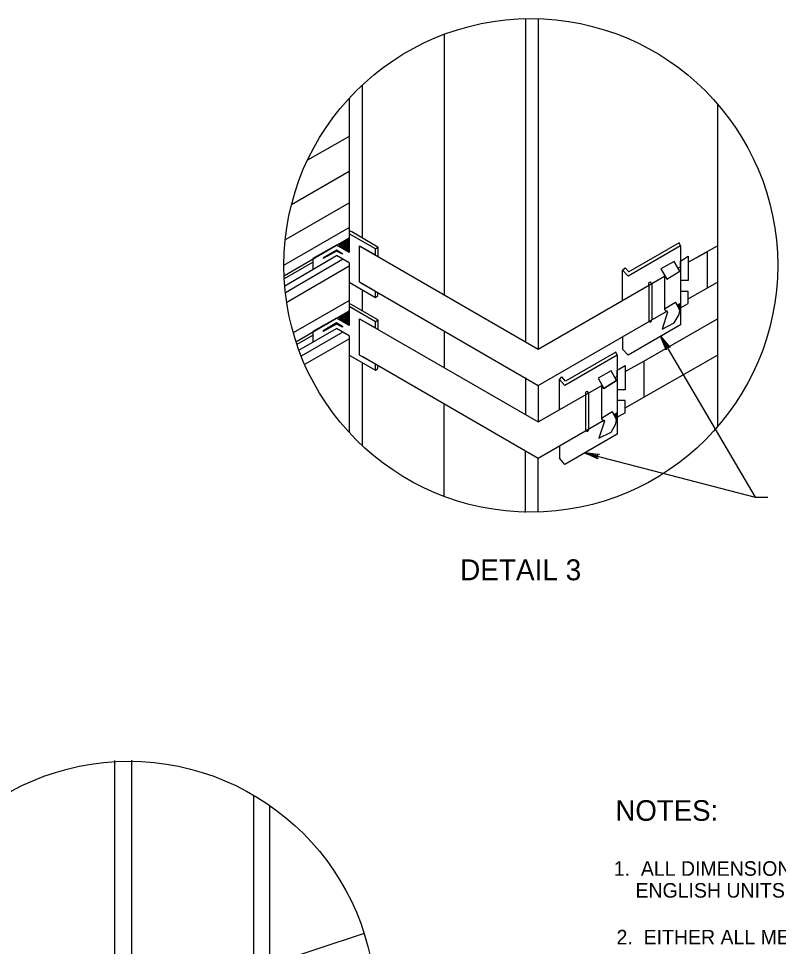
# Model space of a CAD drawing. Extents: x 650495 to 651400, y 297864 to 299646.
# Drawn here: x 650997.2 to 651153.6, y 298064.9 to 298255.9 of the extents above; entities that cross this region are included whole.
import ezdxf

# ---------------------------------------------------------------- set-up
doc = ezdxf.new("R2010")
doc.units = 0
doc.layers.add('2', color=7, linetype='Continuous')
doc.layers.add('3', color=7, linetype='Continuous')

# ---------------------------------------------------------------- blocks, each defined once
blk = doc.blocks.new('RARROW')
at = {"layer": '3'}
blk.add_lwpolyline([(-2.2695, 0.285), (-2.184875, 0.12075), (0, 0), (-2.2695, 0.285), (-2.38575, 0.384625), (0, 0), (-2.183125, -0.108), (-2.262875, -0.2705), (0, 0), (-2.38575, -0.379125), (-2.262875, -0.2705)], dxfattribs=at)

msp = doc.modelspace()

# ---------------------------------------------------------------- linework, layer by layer
at = {"layer": '2'}
for p, q in [((651101.56, 298255.88), (651101.56, 298189.5)), ((651104.19, 298255.88), (651104.19, 298187.88)), ((651084.81, 298252.63), (651084.81, 298199.13)), ((651067.94, 298242.25), (651067.94, 298210.75)), ((651065.31, 298239.5), (651065.31, 298207.75)), ((651141.06, 298238.38), (651141.06, 298171.88)), ((651065.31, 298231.63), (651056.69, 298226.75)), ((651053.44, 298217.63), (651065.31, 298224.5)), ((651052.31, 298210.5), (651065.31, 298218)), ((651051.81, 298205.13), (651065.31, 298212.88)), ((651051.94, 298203), (651065.31, 298210.75)), ((651063.31, 298208.88), (651065.31, 298210)), ((651065.31, 298207.75), (651062.69, 298209.25)), ((651071.19, 298208.88), (651071.19, 298207)), ((651133.44, 298209.13), (651122.69, 298202.88)), ((651133.19, 298209.75), (651122.81, 298203.75)), ((651133.44, 298209.13), (651133.19, 298209.75)), ((651133.44, 298209.13), (651133.44, 298192.88)), ((651141.06, 298209.13), (651141.06, 298201.63)), ((651052.06, 298200.88), (651062.69, 298207.13)), ((651052.19, 298199.5), (651063.94, 298206.38)), ((651057.81, 298206.5), (651057.81, 298204.25)), ((651059.94, 298206.63), (651059.94, 298206.5)), ((651065.31, 298205.63), (651062.69, 298207.13)), ((651063.94, 298207.5), (651063.94, 298207.38)), ((651135.06, 298205.75), (651138.94, 298207.88)), ((651138.94, 298207.88), (651138.94, 298200.38)), ((651051.94, 298202.38), (651057.81, 298205.75)), ((651052.44, 298197.5), (651065.31, 298205)), ((651065.31, 298205.63), (651065.31, 298192.75)), ((651121.56, 298204.13), (651122.06, 298204.63)), ((651122.81, 298203.75), (651122.06, 298204.63)), ((651121.56, 298197.88), (651121.56, 298204.13)), ((651122.69, 298202.88), (651121.56, 298204.13)), ((651130.19, 298202.88), (651130.19, 298196)), ((651126.94, 298201), (651126.94, 298193.5)), ((651127.56, 298201.38), (651127.56, 298193.88)), ((651128.06, 298201.63), (651128.06, 298201.63)), ((651067.94, 298200.13), (651067.94, 298195.75)), ((651053.81, 298191.25), (651065.31, 298197.88)), ((651130.19, 298196.13), (651132.44, 298197.5)), ((651054.31, 298189.38), (651065.31, 298195.75)), ((651063.31, 298193.88), (651065.31, 298195)), ((651065.31, 298192.75), (651062.69, 298194.25)), ((651071.19, 298193.88), (651071.19, 298192)), ((651133.44, 298192.88), (651122.69, 298186.63)), ((651141.06, 298194.13), (651141.06, 298186.63)), ((651054.94, 298187.63), (651062.69, 298192.13)), ((651055.44, 298186.5), (651063.94, 298191.38)), ((651057.81, 298191.5), (651057.81, 298189.25)), ((651059.94, 298191.63), (651059.94, 298191.5)), ((651065.31, 298190.63), (651062.69, 298192.13)), ((651063.94, 298192.5), (651063.94, 298192.38)), ((651084.81, 298191.63), (651084.81, 298184.13)), ((651054.56, 298188.88), (651057.81, 298190.75)), ((651056.19, 298184.75), (651065.31, 298190)), ((651065.31, 298190.63), (651065.31, 298170.75)), ((651121.56, 298190.38), (651121.56, 298187.88)), ((651129.38, 298190.52), (651148.81, 298157.38)), ((651120.19, 298187.25), (651109.81, 298181.25)), ((651120.44, 298186.63), (651120.19, 298187.25)), ((651122.69, 298186.63), (651121.56, 298187.88)), ((651067.94, 298185.13), (651067.94, 298168)), ((651120.44, 298186.63), (651109.69, 298180.38)), ((651120.44, 298186.63), (651120.44, 298170.38)), ((651122.06, 298183.25), (651125.94, 298185.38)), ((651125.94, 298185.38), (651125.94, 298177.88)), ((651128.06, 298186.63), (651128.06, 298186.63)), ((651101.56, 298182), (651101.56, 298174.5)), ((651108.56, 298181.63), (651109.06, 298182.13)), ((651109.69, 298180.38), (651108.56, 298181.63)), ((651108.56, 298175.38), (651108.56, 298181.63)), ((651109.81, 298181.25), (651109.06, 298182.13)), ((651104.19, 298180.38), (651104.19, 298172.88)), ((651117.19, 298180.38), (651117.19, 298173.5)), ((651113.94, 298178.5), (651113.94, 298171)), ((651114.56, 298178.88), (651114.56, 298171.38)), ((651084.81, 298157.5), (651084.81, 298176.63)), ((651117.19, 298173.63), (651119.44, 298175)), ((651120.44, 298170.38), (651109.69, 298164.13)), ((651101.56, 298154.25), (651101.56, 298167)), ((651108.56, 298167.88), (651108.56, 298165.38)), ((651113.69, 298166.5), (651148.81, 298157.38)), ((651104.19, 298154.38), (651104.19, 298165.38)), ((651109.69, 298164.13), (651108.56, 298165.38)), ((651148.81, 298157.38), (651151.44, 298157.38)), ((651148.81, 298157.38), (651151.44, 298157.38)), ((651017.06, 298034.38), (651017.06, 298103.13)), ((651020.56, 298034.38), (651020.56, 298103.25)), ((651045.69, 298023.13), (651045.69, 298096)), ((651048.94, 298024.88), (651048.94, 298093.88)), ((651048.94, 298061.13), (651068.44, 298067.63))]:
    msp.add_line(p, q, dxfattribs=at)
for points in [[(651070.69, 298208.5), (651071.19, 298208.88), (651065.81, 298212), (651065.31, 298212.25)], [(651065.19, 298210.38), (651063.19, 298209.25), (651065.06, 298208.13), (651065.06, 298210.25), (651063.56, 298209.25), (651064.81, 298208.38), (651064.94, 298209.88), (651063.94, 298209.25), (651064.69, 298208.63), (651064.69, 298209.5), (651064.31, 298209.25), (651064.56, 298209), (651064.56, 298209.25)], [(651067.44, 298201.63), (651067.44, 298209.13), (651070.69, 298207.25), (651070.69, 298208.5), (651065.31, 298211.63), (651065.31, 298207.75)], [(651065.31, 298207.75), (651062.69, 298209.25), (651057.81, 298206.5)], [(651063.94, 298207.5), (651062.69, 298208.25), (651059.94, 298206.63)], [(651067.44, 298209.13), (651104.19, 298187.88), (651130.19, 298202.88)], [(651135.06, 298205.75), (651141.06, 298209.13)], [(651063.94, 298207.38), (651062.69, 298208), (651059.94, 298206.5)], [(651133.44, 298204.75), (651133.44, 298206), (651135.06, 298207), (651135.06, 298202), (651133.44, 298202)], [(651065.31, 298205.63), (651065.31, 298204.13), (651065.31, 298201.63), (651070.69, 298198.5), (651070.69, 298199.75), (651067.44, 298201.63)], [(651132.94, 298204.5), (651133.44, 298204.75)], [(651067.94, 298201.38), (651104.19, 298180.38), (651130.81, 298195.75)], [(651135.06, 298198.25), (651141.06, 298201.63)], [(651070.69, 298198.5), (651071.19, 298198.88), (651071.19, 298199.5)], [(651133.44, 298196.38), (651134.56, 298197), (651135.06, 298197.25), (651135.06, 298199.75), (651133.44, 298199.75)], [(651070.69, 298193.5), (651071.19, 298193.88), (651065.81, 298197), (651065.31, 298197.25)], [(651067.44, 298186.63), (651067.44, 298194.13), (651070.69, 298192.25), (651070.69, 298193.5), (651065.31, 298196.63), (651065.31, 298192.75)], [(651130.19, 298196), (651130.44, 298195.75), (651130.69, 298195.75), (651130.81, 298195.5), (651129.69, 298192), (651132.19, 298193.25), (651133.19, 298195), (651133.31, 298195.88), (651132.44, 298197.5)], [(651132.44, 298197.5), (651133.31, 298195.88), (651133.44, 298197.25), (651132.81, 298196.88), (651133.19, 298196.25), (651133.19, 298197.13), (651132.94, 298196.88), (651133.19, 298196.5)], [(651132.81, 298196.88), (651133.44, 298197.25)], [(651065.19, 298195.38), (651063.19, 298194.25), (651065.06, 298193.13), (651065.06, 298195.25), (651063.56, 298194.25), (651064.81, 298193.38), (651064.94, 298194.88), (651063.94, 298194.25), (651064.69, 298193.63), (651064.69, 298194.5), (651064.31, 298194.25), (651064.56, 298194), (651064.56, 298194.25)], [(651130.81, 298195.5), (651129.69, 298192)], [(651065.31, 298192.75), (651062.69, 298194.25), (651057.81, 298191.5)], [(651063.94, 298192.5), (651062.69, 298193.25), (651059.94, 298191.63)], [(651063.94, 298192.38), (651062.69, 298193), (651059.94, 298191.5)], [(651067.44, 298194.13), (651104.19, 298172.88), (651117.31, 298180.38)], [(651125.94, 298185.38), (651141.06, 298194.13)], [(651065.31, 298190.63), (651065.31, 298189.13), (651065.31, 298186.63), (651070.69, 298183.5), (651070.69, 298184.75), (651067.44, 298186.63)], [(651067.94, 298186.38), (651104.19, 298165.38), (651117.69, 298173.25)], [(651122.06, 298175.75), (651141.06, 298186.63)], [(651070.69, 298183.5), (651071.19, 298183.88), (651071.19, 298184.5)], [(651120.44, 298182.25), (651120.44, 298183.5), (651122.06, 298184.5), (651122.06, 298179.5), (651120.44, 298179.5)], [(651119.94, 298182), (651120.31, 298181.38), (651117.69, 298179.75), (651117.19, 298180.38)], [(651119.94, 298182), (651120.44, 298182.25)], [(651120.44, 298173.88), (651121.56, 298174.5), (651122.06, 298174.75), (651122.06, 298177.25), (651120.44, 298177.25)], [(651117.19, 298173.5), (651117.44, 298173.25), (651117.69, 298173.25), (651117.81, 298173), (651116.69, 298169.5), (651119.19, 298170.75), (651120.19, 298172.5), (651120.31, 298173.38), (651119.44, 298175)], [(651119.44, 298175), (651120.31, 298173.38), (651120.44, 298174.75), (651119.81, 298174.38), (651120.19, 298173.75), (651120.19, 298174.63), (651119.94, 298174.38), (651120.19, 298174)], [(651119.81, 298174.38), (651120.44, 298174.75)], [(651117.81, 298173), (651116.69, 298169.5)]]:
    msp.add_lwpolyline(points, dxfattribs=at)
for points in [[(651133.31, 298203.88), (651132.19, 298205.88), (651129.44, 298204.38), (651130.69, 298202.25)], [(651120.31, 298181.38), (651119.19, 298183.38), (651116.56, 298181.88), (651117.69, 298179.75)]]:
    msp.add_lwpolyline(points, close=True, dxfattribs=at)
for centre in [(651102.66, 298205.11), (651019.94, 298052.18)]:
    msp.add_circle(centre, 50.81, dxfattribs=at)
for centre, radius, start, end in [((651127.2, 298201.29), 0.328, 12.4717, 227.5297), ((651127.21, 298193.77), 0.321, 223.0558, 16.9457), ((651114.21, 298178.79), 0.328, 12.4717, 227.5297), ((651114.22, 298171.27), 0.321, 223.0558, 16.9457)]:
    msp.add_arc(centre, radius, start, end, dxfattribs=at)

# ---------------------------------------------------------------- block references
for p, xscale, yscale, rotation in [((651129.38, 298190.52), 1.2574347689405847, 1.3092961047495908, 120.9356690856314), ((651113.69, 298166.5), 1.257434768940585, 1.3092961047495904, 165.6401293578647)]:
    msp.add_blockref('RARROW', p, dxfattribs=dict(at, xscale=xscale, yscale=yscale, rotation=rotation))

# ---------------------------------------------------------------- texts
for s, height, p in [('DETAIL 3', 4.3, (651088.11, 298140.27)), ('NOTES:', 4.25, (651120.08, 298090.74)), ('1.  ALL DIMENSIONS ARE IN MILLIMETERS UNLESS OTHERWISE NOTED.', 3, (651119.74, 298079.42)), ('    ENGLISH UNITS IN PARENTHESIS ().', 3, (651119.74, 298074.92)), ('2.  EITHER ALL METRIC OR ALL ENGLISH UNITS MUST BE USED ON PLANS.', 3, (651120.31, 298065.29))]:
    msp.add_text(s, height=height, dxfattribs=at).set_placement(p)

doc.saveas('drawing.dxf')
